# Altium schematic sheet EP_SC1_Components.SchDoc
size A4; SheetNumber: 1; SheetTotal: 1
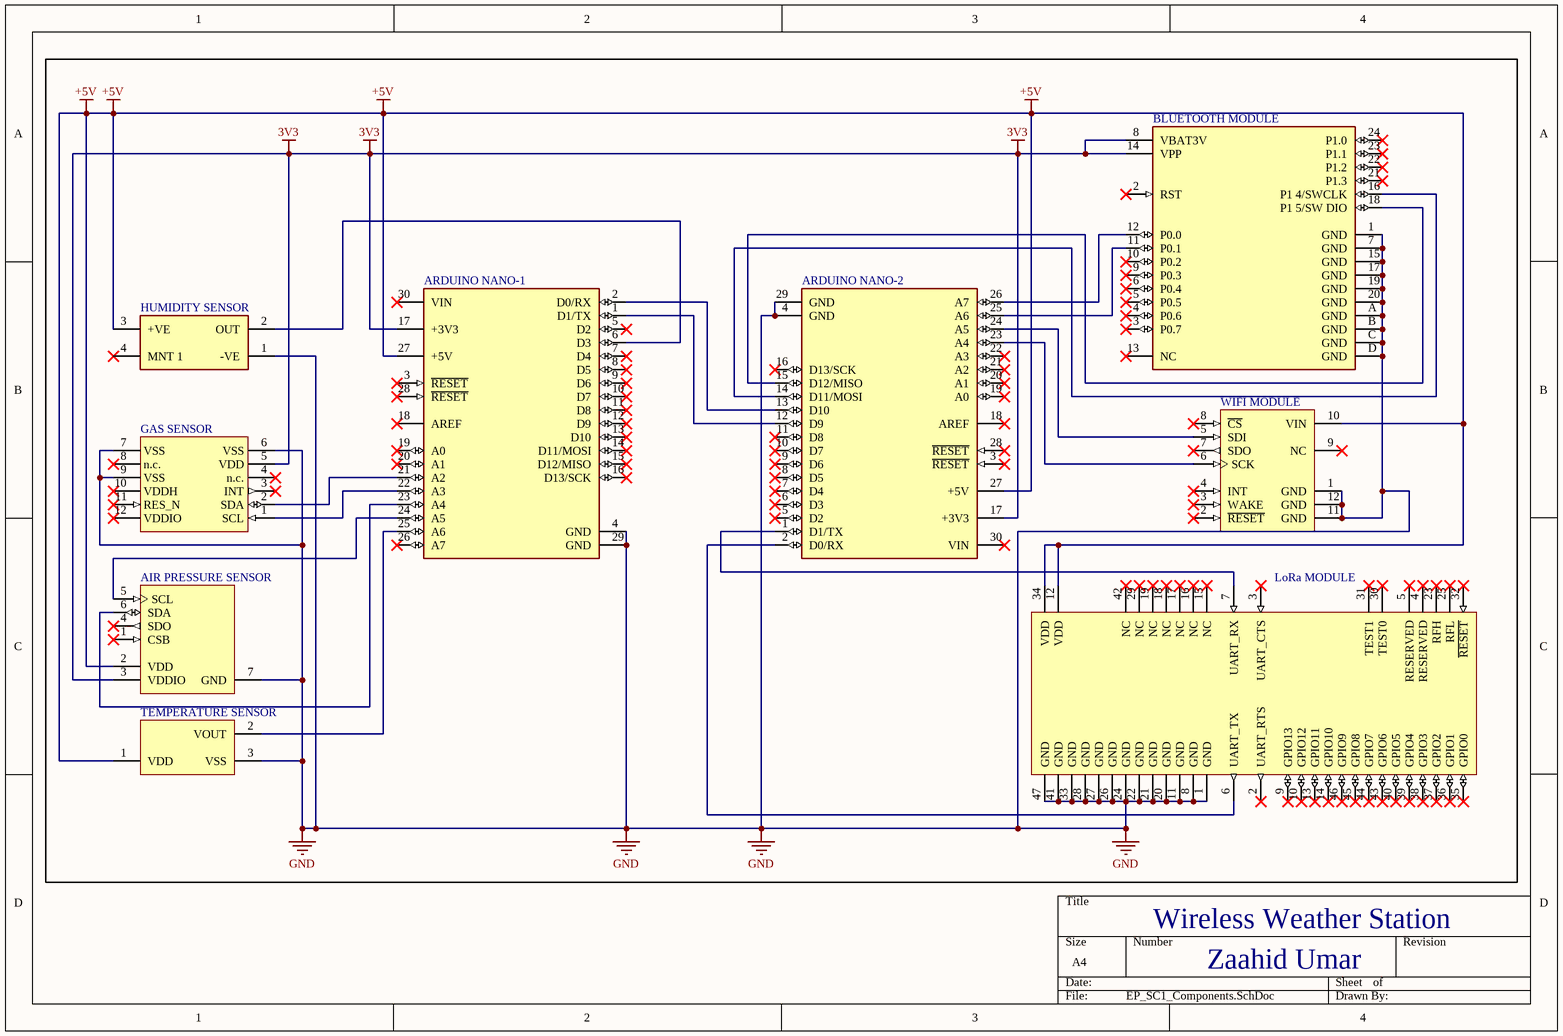
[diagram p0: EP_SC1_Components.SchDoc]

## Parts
AIR_PRESSURE_SENSOR  BMP180  [BOSC-BMP180-7_V]  (value not drawn)
ARDUINO_NANO-1  A000005  [FP-A000005-MFG]  (value not drawn)
ARDUINO_NANO-2  A000005  [FP-A000005-MFG]  (value not drawn)
BLUETOOTH_MODULE  ENW-89846A1KF  [FP-ENW-89846A1KF-MFG]  (value not drawn)
GAS_SENSOR  ZMOD4510AI1V  [ZMODxxxx 12 Leads- LGG12]  (value not drawn)
HUMIDITY_SENSOR  HIH-5031-001  [FP-HIH-5031-001-MFG]  (value not drawn)
LoRa_MODULE  RN2483-I/RM095  [MCHP-RN2483-47_V]  (value not drawn)
TEMPERATURE_SENSOR  TC1047AVNBTR  [SOT-23-NB3_L]  (value not drawn)
WIFI_MODULE  MRF24J40MA-I/RM  [MRF24J40MA]  (value not drawn)

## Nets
3V3: AIR_PRESSURE_SENSOR.3(VDDIO) ARDUINO_NANO-1.17(+3V3) ARDUINO_NANO-2.17(+3V3) BLUETOOTH_MODULE.8(VBAT3V) BLUETOOTH_MODULE.14(VPP) GAS_SENSOR.5(VDD)
+5V: AIR_PRESSURE_SENSOR.2(VDD) ARDUINO_NANO-1.27(+5V) ARDUINO_NANO-2.27(+5V) HUMIDITY_SENSOR.3(+VE) LoRa_MODULE.12(VDD) LoRa_MODULE.34(VDD) TEMPERATURE_SENSOR.1(VDD) WIFI_MODULE.10(VIN)
GND: AIR_PRESSURE_SENSOR.7(GND) ARDUINO_NANO-1.4(GND) ARDUINO_NANO-1.29(GND) ARDUINO_NANO-2.4(GND) ARDUINO_NANO-2.29(GND) BLUETOOTH_MODULE.1(GND) BLUETOOTH_MODULE.7(GND) BLUETOOTH_MODULE.15(GND) BLUETOOTH_MODULE.17(GND) BLUETOOTH_MODULE.19(GND) BLUETOOTH_MODULE.20(GND) BLUETOOTH_MODULE.A(GND) BLUETOOTH_MODULE.B(GND) BLUETOOTH_MODULE.C(GND) BLUETOOTH_MODULE.D(GND) GAS_SENSOR.6(VSS) GAS_SENSOR.7(VSS) GAS_SENSOR.9(VSS) HUMIDITY_SENSOR.1(-VE) LoRa_MODULE.1(GND) LoRa_MODULE.8(GND) LoRa_MODULE.11(GND) LoRa_MODULE.20(GND) LoRa_MODULE.21(GND) LoRa_MODULE.22(GND) LoRa_MODULE.24(GND) LoRa_MODULE.26(GND) LoRa_MODULE.27(GND) LoRa_MODULE.28(GND) LoRa_MODULE.33(GND) LoRa_MODULE.41(GND) LoRa_MODULE.47(GND) TEMPERATURE_SENSOR.3(VSS) WIFI_MODULE.1(GND) WIFI_MODULE.11(GND) WIFI_MODULE.12(GND)
NetAIR_PRESSURE_SENSOR_5: AIR_PRESSURE_SENSOR.5(SCL) ARDUINO_NANO-1.24(A5)
NetAIR_PRESSURE_SENSOR_6: AIR_PRESSURE_SENSOR.6(SDA) ARDUINO_NANO-1.23(A4)
NetARDUINO_NANO-1_1: ARDUINO_NANO-1.1(D1/TX) ARDUINO_NANO-2.12(D9)
NetARDUINO_NANO-1_2: ARDUINO_NANO-1.2(D0/RX) ARDUINO_NANO-2.13(D10)
NetARDUINO_NANO-1_6: ARDUINO_NANO-1.6(D3) HUMIDITY_SENSOR.2(OUT)
NetARDUINO_NANO-1_21: ARDUINO_NANO-1.21(A2) GAS_SENSOR.2(SDA)
NetARDUINO_NANO-1_22: ARDUINO_NANO-1.22(A3) GAS_SENSOR.1(SCL)
NetARDUINO_NANO-1_25: ARDUINO_NANO-1.25(A6) TEMPERATURE_SENSOR.2(VOUT)
NetARDUINO_NANO-2_1: ARDUINO_NANO-2.1(D1/TX) LoRa_MODULE.7(UART_RX)
NetARDUINO_NANO-2_2: ARDUINO_NANO-2.2(D0/RX) LoRa_MODULE.6(UART_TX)
NetARDUINO_NANO-2_14: ARDUINO_NANO-2.14(D11/MOSI) BLUETOOTH_MODULE.16(P1_4/SWCLK)
NetARDUINO_NANO-2_15: ARDUINO_NANO-2.15(D12/MISO) BLUETOOTH_MODULE.18(P1_5/SW_DIO)
NetARDUINO_NANO-2_23: ARDUINO_NANO-2.23(A4) WIFI_MODULE.6(SCK)
NetARDUINO_NANO-2_24: ARDUINO_NANO-2.24(A5) WIFI_MODULE.5(SDI)
NetARDUINO_NANO-2_25: ARDUINO_NANO-2.25(A6) BLUETOOTH_MODULE.11(P0.1)
NetARDUINO_NANO-2_26: ARDUINO_NANO-2.26(A7) BLUETOOTH_MODULE.12(P0.0)

Not connected (* = marked no-connect by the designer): AIR_PRESSURE_SENSOR 1(CSB)* 4(SDO)*; ARDUINO_NANO-1 3(~{RESET})* 5(D2)* 7(D4)* 8(D5)* 9(D6)* 10(D7)* 11(D8)* 12(D9)* 13(D10)* 14(D11/MOSI)* 15(D12/MISO)* 16(D13/SCK)* 18(AREF)* 19(A0)* 20(A1)* 26(A7)* 28(~{RESET})* 30(VIN)*; ARDUINO_NANO-2 3(~{RESET})* 5(D2)* 6(D3)* 7(D4)* 8(D5)* 9(D6)* 10(D7)* 11(D8)* 16(D13/SCK)* 18(AREF)* 19(A0)* 20(A1)* 21(A2)* 22(A3)* 28(~{RESET})* 30(VIN)*; BLUETOOTH_MODULE 2(RST)* 3(P0.7)* 4(P0.6)* 5(P0.5)* 6(P0.4)* 9(P0.3)* 10(P0.2)* 13(NC)* 21(P1.3)* 22(P1.2)* 23(P1.1)* 24(P1.0)*; GAS_SENSOR 3(INT)* 4(n.c.)* 8(n.c.)* 10(VDDH)* 11(RES_N)* 12(VDDIO)*; HUMIDITY_SENSOR 4(MNT_1)*; LoRa_MODULE 2(UART_RTS)* 3(UART_CTS)* 4(RESERVED)* 5(RESERVED)* 9(GPIO13)* 10(GPIO12)* 13(GPIO11)* 14(GPIO10)* 15(NC)* 16(NC)* 17(NC)* 18(NC)* 19(NC)* 23(RFH)* 25(RFL)* 29(NC)* 30(TEST0)* 31(TEST1)* 32(~{RESET})* 35(GPIO0)* 36(GPIO1)* 37(GPIO2)* 38(GPIO3)* 39(GPIO4)* 40(GPIO5)* 42(NC)* 43(GPIO6)* 44(GPIO7)* 45(GPIO8)* 46(GPIO9)*; WIFI_MODULE 2(~{RESET})* 3(WAKE)* 4(INT)* 7(SDO)* 8(~{CS})* 9(NC)*

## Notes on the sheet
- Wireless Weather Station
- Zaahid Umar

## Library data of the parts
AIR_PRESSURE_SENSOR = CMP-2000-05074-1: Digital Pressure Sensor, 1.8 to 3.6 V, -40 to 85 degC, 7-Pin LGA, RoHS; Manufacturer: Bosch Sensortec; Output Type: I²C; Other Names: 0273.300.244-1NV / 828-1027-2; Pressure Type: Absolute; Maximum Pressure: 145.04PSI(1000kPa); Voltage - Supply: 1.62V~3.6V; EDA / CAD Models: DownloadfromAcceleratedDesigns; Accuracy: ±2%; Port Style: NoPort; For Use With: 1528-1434-ND / -BMP180BAROMETRICPRESS/TEMP5V / 1528-1435-ND / -L3GD20HLSM303BMP18010DOFIMU / 1568-1260-ND / -SPARKFUNBAROMETRICPRESSURESEN / 1597-1301-ND / -GROVEBAROMETERSENSOR / 1597-1302-ND / -GROVEIMU10DOF / 1471-1581-ND / -10DOFCLICK / 101040003-ND / -XADOWBAROMETERBMP180V1.0 / 101040004-ND / -XADOW-IMU10DOF / 114990245-ND / -BOARDTPHPRESSURETEMPREV.4 / 828-1028-ND / -BMP180SHUTTLEBOARDFORDEVKIT / 103990031-ND / -TPHBOARDTHETEMPERATUREPRESSU; Operating Pressure: 4.35PSI~15.95PSI(30kPa~110kPa); Output: 16~19b
ARDUINO_NANO-1 ARDUINO_NANO-2 = CMP-189986-000002-1: ARDUINO NANO ATMEGA328 EVAL BRD; Number of Bits: 8; Evaluation Kit: Yes; Operating Supply Voltage: 12V; Interface: I2C; Data Bus Width: 8b; Core Architecture: AVR
BLUETOOTH_MODULE = CMP-05527-000002-1: RF TXRX MOD BLUETOOTH CHIP ANT; Manufacturer: Panasonic; Number Of Gpio: 14; Number Of Adc Channels: 4; Max Frequency: 2.4GHz; Interface: I2C,SPI,UART; Sensitivity: -93dBm; Receiving Current: 4.9mA; Max Supply Voltage: 3.3V; Data Rate: 1Mbits/s; Min Supply Voltage: 2.35V
GAS_SENSOR = CMP-00572-100129191-1: ZMOD4510AI1V ZMOD4510 Series 3.6 V 11 mA Gas Sensor Module for Outdoor Air Quality - LGA-12
HUMIDITY_SENSOR = CMP-11179-000003-1: SENSOR HUMIDITY 5V ANALOG 3% SMD; Min Supply Voltage: 2.7V; Nominal Supply Current: 500uA; Operating Supply Current: 200uA; Max Supply Voltage: 5.5V; Response Time: 5s; Sensing Method: Capacitive; Output Type: Analog Voltage; Operating Supply Voltage: 3.3V
LoRa_MODULE = CMP-2000-05219-1: Low-Power Long Range LoRa(TM) Technology Transceiver Module, 2.1 to 3.6 V, -40 to 85 degC, 47-Pin SMD, RoHS; Manufacturer: Microchip; Minimum Operating Supply Voltage: 2.1V; Maximum Operating Supply Voltage: 3.6V; Operating Band Frequency Range: 438,868MHz
TEMPERATURE_SENSOR = CMP-0192-00223-1: Precision Temperature-to-Voltage Converter, 3-Pin SOT-23, Extended Temperature, Tape and Reel
WIFI_MODULE = CMP-0191-00063-1: 2.4 GHz IEEE Std. 802.15.4, RF Transceiver 12-Pin Module, Industrial Temperature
